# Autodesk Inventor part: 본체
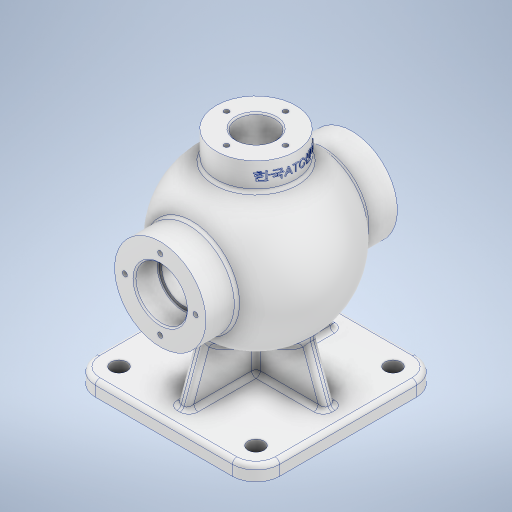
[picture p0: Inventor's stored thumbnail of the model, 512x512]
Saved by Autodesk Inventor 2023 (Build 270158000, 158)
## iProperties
Created: 2023-07
Part Number: 본체
Material: 알루미늄 6061
Document SubType Name: Modeling
Designer: Owner
Density: 2.7 g/cm^3
Appearance: 알루미늄 - 평지
Mass: 1526.21 g
Surface Area: 1175.12 cm^2
Volume: 565.262 cm^3
Author: Owner
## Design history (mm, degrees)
sketch "스케치1"
  geometry: L1 (62.5, 62.5)-(-62.5, 62.5); L2 (-62.5, 62.5)-(-62.5, -62.5); L3 (-62.5, -62.5)-(62.5, -62.5); L4 (62.5, -62.5)-(62.5, 62.5); L5 (62.5, 62.5)-(-62.5, -62.5); L6 (-62.5, 62.5)-(62.5, -62.5); 1 further point
  constraints: 12 end point, 2 midpoint, 2 parallel, 2 perpendicular, 1 horizontal
  dimensions: "d0" = 125 distance of L2.end L3.end
extrude "돌출1" new body sketch "스케치1" distance "d1" = 10; taper "d2" = 0 deg
sketch "스케치2"
  geometry: L1 (0, 62.5)-(0, -62.5) reference; L2 (85, 54)-(85, -54); A1 r 54 centre (85, 0) between (85, -54) and (85, 54); 4 further points
  constraints: 3 midpoint, 2 end point, 2 point on circle, 1 centre point, 1 coincident, 1 horizontal alignment, 1 vertical
  dimensions: "d3" = 108 diameter of A1; "d4" = 85 distance of point (0, 0) point (85, 0)
revolve "회전1" sketch "스케치2" stored, may be unused: angle "d5" = 90 deg
sketch "스케치3"
  geometry: L1 (62.5, 10)-(62.5, 0) reference; L2 (62.5, 0)-(-62.5, 0) reference; L3 (-62.5, 0)-(-62.5, 10) reference; L4 (-62.5, 10)-(62.5, 10) reference; C1 r 54 at (0, 85) reference; C2 r 31 at (0, 85); 1 further point
  constraints: 1 centre point, 1 coincident
  dimensions: "d6" = 62 diameter of C2
extrude "돌출2" join sketch "스케치3" stored distance "d7" = 130; taper "d8" = 0 deg
node "작업 평면1"
sketch "스케치4"
  geometry: C1 r 27 at (0, 0); 1 further point
  constraints: 1 centre point, 1 coincident
  dimensions: "d10" = 54 diameter of C1
extrude "돌출3" join sketch "스케치4" stored distance "d11" = 130; taper "d12" = 0 deg
sketch "스케치5"
  geometry: L1 (54, 44.215)-(54, 65) reference; L2 (54, 65)-(116, 65) reference; L3 (116, 65)-(116, 44.215) reference; L4 (131.765, 27)-(150, 27) reference; L5 (150, 27)-(150, -27) reference; L6 (150, -27)-(131.765, -27) reference; L7 (116, -44.215)-(116, -65) reference; L8 (116, -65)-(54, -65) reference; L9 (54, -65)-(54, -44.215) reference; L10 (0, 62.5)-(10, 62.5) reference; L11 (10, 62.5)-(10, -62.5) reference; L12 (10, -62.5)-(0, -62.5) reference; L13 (0, -62.5)-(0, 62.5) reference; L14 (10, -62.5)-(10, 62.5) reference; L15 (10, 50.5)-(80, 25.022); L16 (80, 25.022)-(80, -25.022); L17 (80, -25.022)-(10, -50.5); A1 r 54 centre (85, 0) between (54, 44.215) and (54, -44.215) reference; A2 r 54 centre (85, 0) between (131.765, 27) and (116, 44.215) reference; A3 r 54 centre (85, 0) between (116, -44.215) and (131.765, -27) reference; 5 further points
  constraints: 6 end point, 2 point on line, 1 parallel
  dimensions: "d13" = 12 distance from line of L10 L15.start; "d14" = 20 deg angle of L10 L15; "d15" = 20 deg angle of L12 L17; "d16" = 12 distance of L11.end L17.end; "d17" = 80 distance between parallel lines of L13 L16
extrude "돌출4" join sketch "스케치5" stored distance "d18" = 8; taper "d19" = 0 deg
sketch "스케치6"
  geometry: L1 (-27, 131.765)-(-27, 150) reference; L2 (-27, 150)-(27, 150) reference; L3 (27, 150)-(27, 131.765) reference; L4 (-4, 10)-(-4, 31.148) reference; L5 (-62.5, 10)-(-4, 10) reference; L6 (-62.5, 0)-(-62.5, 10) reference; L7 (62.5, 0)-(-62.5, 0) reference; L8 (62.5, 10)-(62.5, 0) reference; L9 (4, 10)-(62.5, 10) reference; L10 (4, 31.148)-(4, 10) reference; L11 (62.5, 10)-(-62.5, 10) reference; L12 (50.5, 10)-(42.103, 33.069); A1 r 54 centre (0, 85) between (4, 31.148) and (27, 131.765) reference; A2 r 54 centre (0, 85) between (-27, 131.765) and (-4, 31.148) reference; 1 further point
  constraints: 2 end point, 1 point on line
  dimensions: "d20" = 12 distance of L8.start L12.start; "d21" = 20 deg angle of L8 L12
feature "리브1" sketch "스케치6" dims "d22" = 1, "d23" = 8, "d24" = 0, "d25" = 0, "d26" = 1, "d27" = 1
sketch "스케치7"
  geometry: L1 (46.034, -37.385)-(10, -50.5) reference; L2 (10, -50.5)-(10, -62.5) reference; L3 (10, -62.5)-(0, -62.5) reference; L4 (0, -62.5)-(0, 62.5) reference; L5 (0, 62.5)-(10, 62.5) reference; L6 (10, 62.5)-(10, 50.5) reference; L7 (10, 50.5)-(46.034, 37.385) reference; L8 (116, -44.215)-(116, -65) reference; L9 (116, -65)-(54, -65) reference; L10 (54, -65)-(54, -44.215) reference; L11 (150, -27)-(131.765, -27) reference; L12 (150, 27)-(150, -27) reference; L13 (131.765, 27)-(150, 27) reference; L14 (54, 44.215)-(54, 65) reference; L15 (54, 65)-(116, 65) reference; L16 (116, 65)-(116, 44.215) reference; L17 (85, 44)-(85, -44); L18 (54, -44.215)-(116, -44.215) reference; A1 r 54 centre (85, 0) between (116, -44.215) and (131.765, -27) reference; A2 r 54 centre (85, 0) between (46.034, -37.385) and (54, -44.215) reference; A3 r 54 centre (85, 0) between (54, 44.215) and (46.034, 37.385) reference; A4 r 54 centre (85, 0) between (131.765, 27) and (116, 44.215) reference; A5 r 44 centre (85, 0) between (85, -44) and (85, 44); 1 further point
  constraints: 2 end point, 2 point on circle, 1 centre point, 1 coincident, 1 midpoint, 1 perpendicular
  dimensions: "d28" = 88 diameter of A5
revolve "회전2" sketch "스케치7" stored, may be unused: angle "d29" = 90 deg
sketch "스케치8"
  geometry: C1 r 31 at (0, 0) reference; C2 r 17.5 at (0, 0); 1 further point
  constraints: 1 centre point, 1 coincident
  dimensions: "d30" = 35 diameter of C2
extrude "돌출5" cut sketch "스케치8" distance "d31" = 16; taper "d32" = 0 deg
sketch "스케치9"
  geometry: C1 r 17.5 at (0, 0) reference; C2 r 15 at (0, 0); 1 further point
  constraints: 1 centre point, 1 coincident
  dimensions: "d33" = 30 diameter of C2
extrude "돌출6" cut sketch "스케치9" extent not by distance; stored distance "d34" = 16; taper "d35" = 0 deg
sketch "스케치10"
  geometry: C1 r 17.5 at (0, 0) reference; 2 further points
  constraints: 1 vertical alignment
  dimensions: "d36" = 24 distance of C1.centre point (0, 24)
hole "구멍1" sketch "스케치10" at (0, 24) diameter "d37" = 3.45873; stored, may be unused: countersink angle "d41" = 90 deg, drill point angle "d43" = 118 deg; dims "d38" = 12, "d39" = 8, "d40" = 4.4, "d42" = 15
sketch "스케치11"
  geometry: C1 r 27 at (0, 0) reference; C2 r 13 at (0, 0)
  constraints: 1 centre point, 1 coincident
  dimensions: "d47" = 26 diameter of C2
extrude "돌출7" cut sketch "스케치11" stored distance "d48" = 10; taper "d49" = 0 deg
sketch "스케치12"
  geometry: C1 r 13 at (0, 0) reference; 1 further point
  constraints: 1 vertical alignment
  dimensions: "d50" = 20 distance of C1.centre point (0, 20)
hole "구멍2" sketch "스케치12" at (0, 20) diameter "d51" = 3.45873; stored, may be unused: countersink angle "d55" = 90 deg, drill point angle "d57" = 118 deg; dims "d52" = 9, "d53" = 4, "d54" = 2, "d56" = 11
fillet "모깎기1" dims "d61" = 16
sketch "스케치13"
  geometry: C1 r 5.5 at (46.5, -46.5); A1 r 16 centre (46.5, -46.5) between (46.5, -62.5) and (62.5, -46.5) reference; 1 further point
  constraints: 1 centre point, 1 coincident
  dimensions: "d62" = 11 diameter of C1
extrude "돌출8" cut sketch "스케치13" extent not by distance; stored distance "d63" = 0; taper "d64" = 0 deg
fillet "모깎기2" dims "d68" = 3
fillet "모깎기3" dims "d69" = 3
fillet "모깎기4" dims "d70" = 3
fillet "모깎기5" dims "d71" = 3
fillet "모깎기6" dims "d72" = 0.6
chamfer "모따기1" distance "d73" = 1; stored, may be unused: second distance "d74" = 2, angle "d75" = 45 deg
node "작업 평면2"
sketch "스케치14"
  geometry: L1 (150, 27)-(150, -27) reference; L2 (-30, 0)-(180, 0) reference; 2 further points
  constraints: 1 point on line, 1 other
  dimensions: "d77" = 9 distance from line of L1 point (141, 0)
feature "엠보싱1" sketch "스케치14" dims "d78" = 0.5, "d79" = 0
fillet "모깎기7" dims "d80" = 3
feature "ρ耀σ耀υ耀χ耀ω耀ϋ耀ύ耀Ϗ耀" dims "d0" = 125, "d1" = 10, "d2" = 0, "d3" = 108, "d4" = 85, "d5" = 90 deg, "d6" = 62, "d7" = 130, "d8" = 0, "d9" = -150, "d10" = 54, "d11" = 130, "d12" = 0, "d13" = 12, "d14" = 20 deg, "d15" = 20 deg, "d16" = 12, "d17" = 80, "d18" = 8, "d19" = 0, "d20" = 12, "d21" = 20 deg, "d22" = 1, "d23" = 8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
node "솔리드1"
mirror "미러1"
mirror "미러2"
pattern_circular "원형 패턴1" dims angle "d45" = 360 deg
mirror "미러3"
pattern_circular "원형 패턴2" dims angle "d59" = 360 deg
pattern_circular "원형 패턴3" dims angle "d66" = 360 deg
node "절단 모서리 투영1"
node "절단 모서리 투영2"
node "절단 모서리 투영3"
node "절단 모서리 투영4"
feature "A9D066F2-1C7D-4E18-AEED-F7BC21143FA4" dims "d37" = 3.45873, "d38" = 12, "d39" = 8, "d40" = 4.4, "d41" = 90 deg, "d42" = 15, "d43" = 118 deg
